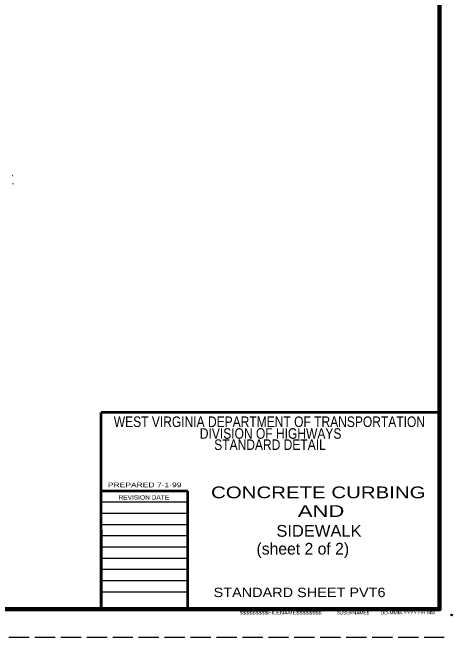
# Model space of a CAD drawing. Extents: x 75.6 to 110.9, y 28 to 50.
# Drawn here: x 103.14 to 110.94, y 27.98 to 39.07 of the extents above; entities that cross this region are included whole.
import ezdxf
from ezdxf.enums import TextEntityAlignment as Align

# ---------------------------------------------------------------- set-up
doc = ezdxf.new("R2010")
doc.units = 0
doc.header["$LTSCALE"] = 0.06
doc.header["$PDMODE"] = 32
doc.header["$PDSIZE"] = 0.03
doc.linetypes.add('LONG_DASHED', pattern=[7.5, 6, -1.5])
doc.layers.add('1', color=7, linetype='Continuous', lineweight=25)

msp = doc.modelspace()

# ---------------------------------------------------------------- linework, layer by layer
at = {"layer": '1'}
for p, q in [((103.14992, 36.18217), (103.14592, 36.17533)), ((103.14592, 36.17533), (103.14992, 36.17533)), ((103.14758, 36.03392), (103.1475, 36.02225)), ((103.14758, 36.03392), (103.1475, 36.02225)), ((103.1475, 36.02225), (103.14992, 36.02358)), ((103.1475, 36.02225), (103.14992, 36.02358)), ((103.14992, 36.03258), (103.14758, 36.03392)), ((103.14992, 36.03258), (103.14758, 36.03392)), ((106.25458, 30.37892), (104.71667, 30.37892)), ((106.25458, 30.17992), (104.71667, 30.17992)), ((106.25458, 29.98092), (104.71667, 29.98092)), ((106.25458, 29.78192), (104.71667, 29.78192)), ((106.25458, 29.58292), (104.71667, 29.58292)), ((106.25458, 29.38392), (104.71667, 29.38392)), ((106.25458, 29.18492), (104.71667, 29.18492)), ((106.25458, 28.98592), (104.71667, 28.98592)), ((106.25458, 28.78692), (104.71667, 28.78692))]:
    msp.add_line(p, q, dxfattribs=at)
at = {"layer": '1', "lineweight": 53}
for p, q in [((110.71667, 31.96975), (104.71667, 31.96975)), ((104.71667, 28.47992), (104.71667, 31.96975)), ((110.71667, 28.47992), (110.71667, 30.97892)), ((106.25458, 30.57892), (104.71667, 30.57892)), ((106.25458, 28.47992), (106.25458, 30.57892)), ((104.71667, 29.88992), (104.71667, 28.47992)), ((110.71667, 28.47992), (104.71667, 28.47992))]:
    msp.add_line(p, q, dxfattribs=at)
at = {"layer": '1', "linetype": 'LONG_DASHED'}
msp.add_line((110.8, 27.97992), (75.6, 27.97992), dxfattribs=at)
at = {"layer": '1', "lineweight": 158}
msp.add_lwpolyline([(110.71667, 49.47992), (110.71667, 28.47992), (78.21667, 28.47992)], dxfattribs=at)
at = {"layer": '1'}
for p in [(110.71667, 28.47992), (110.92967, 28.37992)]:
    msp.add_point(p, dxfattribs=at)

# ---------------------------------------------------------------- texts
for s, height, width, p in [('WEST VIRGINIA DEPARTMENT OF TRANSPORTATION', 0.1875, 0.85, (107.69842, 31.71483)), ('DIVISION OF HIGHWAYS', 0.1875, 0.85, (107.72029, 31.50592)), ('STANDARD DETAIL', 0.1875, 0.85, (107.709, 31.30775)), (' PREPARED 7-1-99 ', 0.08333, 1.35, (105.4875, 30.64575)), ('    CONCRETE CURBING    ', 0.2083, 1.3, (108.56587, 30.45092)), ('  AND  ', 0.2083, 1.4, (108.61479, 30.11917)), (' SIDEWALK', 0.2083, 1.05, (108.53663, 29.76775)), ('STANDARD SHEET PVT6      ', 0.1667, 1.15, (108.44683, 28.697))]:
    msp.add_text(s, height=height, dxfattribs=dict(at, width=width)).set_placement(p, align=Align.CENTER)
for s, height, width, p in [('REVISION DATE', 0.079, 1.1, (105.02375, 30.42625)), ('$$$$$$$$$FILENAME$$$$$$$$', 0.06, 1.25, (107.17242, 28.38817)), ('$USERNAME$', 0.06, 1.05, (108.8965, 28.38817)), ('DD-MMM-YYYY HH:MM', 0.06, 1.1, (109.67008, 28.38817))]:
    msp.add_text(s, height=height, dxfattribs=dict(at, width=width)).set_placement(p)
msp.add_text('     (sheet 2 of 2)     ', height=0.2083, dxfattribs=at).set_placement((108.29054, 29.451), align=Align.CENTER)

doc.saveas('drawing.dxf')
